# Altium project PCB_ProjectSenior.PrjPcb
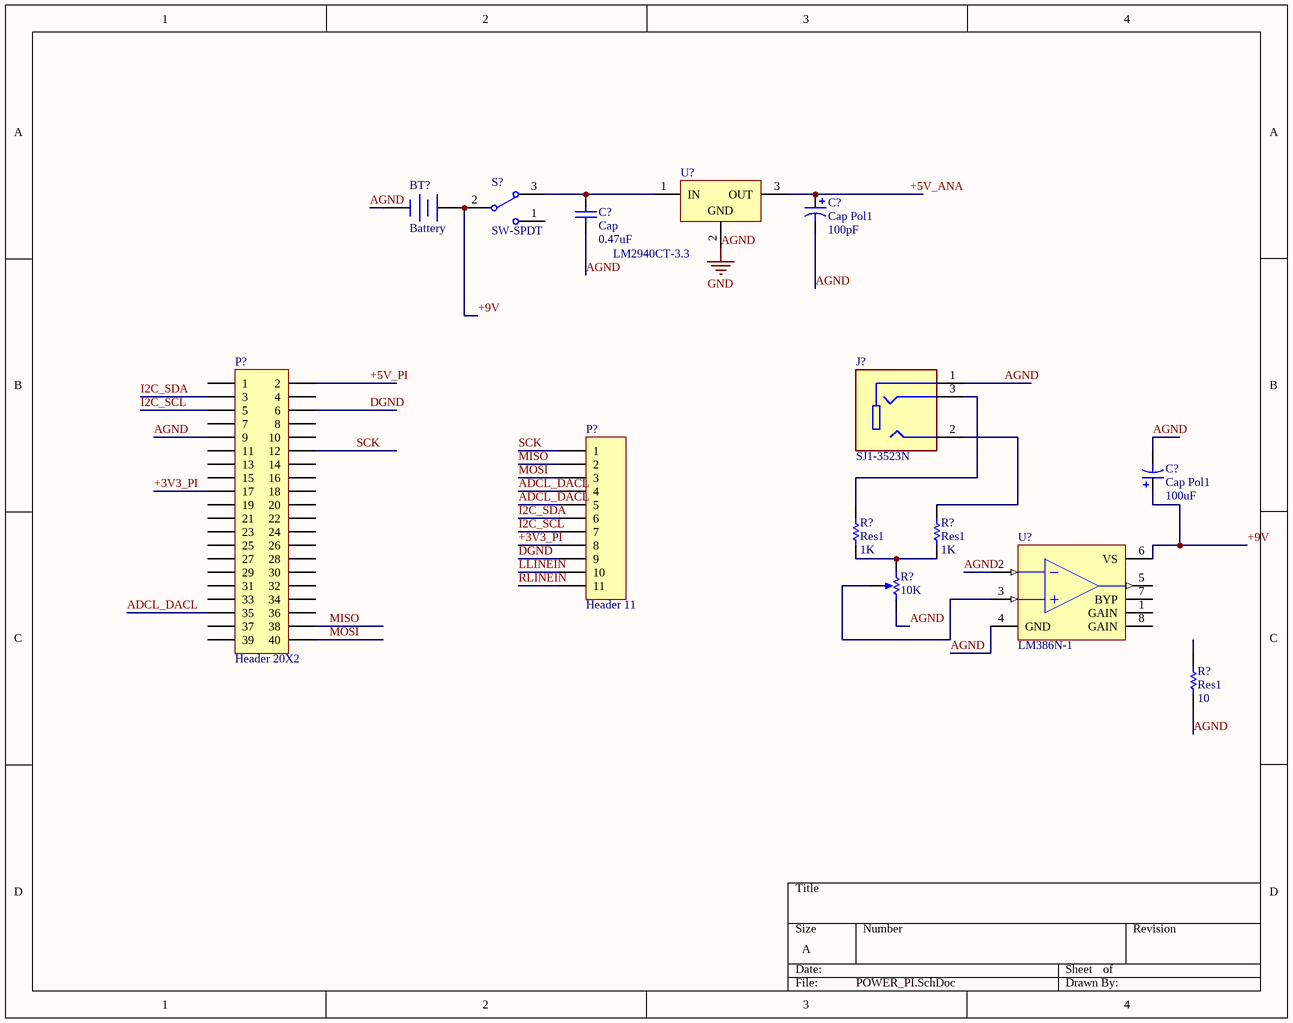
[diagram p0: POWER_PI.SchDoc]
2 sheets, 14 parts. Net scope: global (net labels, ports and power ports of the same name join across sheets).
Sheets:
  POWER_PI.SchDoc
  CODEC_INTERFACE.SchDoc

## Sheet POWER_PI.SchDoc
size A; SheetNumber: 1; SheetTotal: 2

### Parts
(Parts that share a designator on the sheet are numbered #1, #2 ... from top to bottom, then left to right.)
BT?  Battery  [BAT-2]
C?#1  Cap Pol1  value 100pF  [RB7.6-15]
C?#2  Cap  value 0.47uF  [RAD-0.3]
C?#3  Cap Pol1  value 100uF  [RB7.6-15]
J?  SJ1-3523N  [CUI_SJ1-3523N]
P?#1  Header 20X2  [HDR2X20]
P?#2  Header 11  [HDR1X11]
R?#1  Res1  value 1K  [AXIAL-0.3]
R?#2  Res1  value 1K  [AXIAL-0.3]
R?#3  value 10K  [POT OFFSET 200]  (hidden comment: RPot_3)
R?#4  Res1  value 10  [AXIAL-0.3]
S?  SW-SPDT  [SW DPST jameco]
U?#1  LM2940CT-3.3  [T03B]
U?#2  LM386N-1  [DIP-8]

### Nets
AGND: BT?.2(-) C?#1.2 C?#2.1 C?#3.2 J?.1 P?#1.9 R?#3.3(BOT) R?#4.1 U?#1.2(GND) U?#2.2(IN-) U?#2.4(GND)  [also labelled GND]
+3V3_PI: P?#1.17 P?#2.8
+5V_ANA: C?#1.1 U?#1.3(OUT)
+5V_PI: P?#1.2
+9V: BT?.1(+) C?#3.1 S?.2 U?#2.6(VS)
ADCL_DACL: P?#1.35 P?#2.4 P?#2.5
DGND: P?#1.6 P?#2.9
I2C_SCL: P?#1.5 P?#2.7
I2C_SDA: P?#1.3 P?#2.6
LLINEIN: P?#2.10
MISO: P?#1.38 P?#2.2
MOSI: P?#1.40 P?#2.3
RLINEIN: P?#2.11
SCK: P?#1.12 P?#2.1
NetC?#2_2: C?#2.2 S?.3 U?#1.1(IN)
NetJ?_2: J?.2 R?#2.2
NetJ?_3: J?.3 R?#1.2
NetR?#1_1: R?#1.1 R?#2.1 R?#3.1(TOP)
NetR?#3_2: R?#3.2(TAP) U?#2.3(IN+)

Not connected (* = marked no-connect by the designer): P?#1 1 4 7 8 10 11 13 14 15 16 18 19 20 21 22 23 24 25 26 27 28 29 30 31 32 33 34 36 37 39; R?#4 2; S? 1; U?#2 1(GAIN) 5(OUT) 7(BYP) 8(GAIN)

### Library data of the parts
BT? = Battery: Multicell Battery
C?#1 C?#3 = Cap Pol1: Polarized Capacitor (Radial)
C?#2 = Cap: Capacitor
J? = SJ1-3523N: 3.5 mm, Stereo, Right Angle, Through Hole, 3 Conductors, 0 Internal Switches, Audio Jack Connector; MF: Same Sky
P?#1 = Header 20X2: Header, 20-Pin, Dual row
P?#2 = Header 11: Header, 11-Pin
R?#1 R?#2 R?#4 = Res1: Resistor
R?#3 = RPot: Potentiometer; Sim Note: Enter the Resistance value and the set point into parameter fields.; Set Position: 0.5
S? = SW-SPDT: SPDT Subminiature Toggle Switch, Right Angle Mounting, Vertical Actuation
U?#1 = LM2940CT-5.0: 1A Low Dropout Regulator, 3-pin TO-220; Manufacturer: National Semiconductor; PackageTopMarking: NSUZXYTTE#*LM2940CT*-5.0 P+; PowerWise: N; CompType: LDO IC; High-Reliability: Y
U?#2 = LM386N-1: Low-Voltage Audio Power Amplifier

## Sheet CODEC_INTERFACE.SchDoc
size A; SheetNumber: 2; SheetTotal: 2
